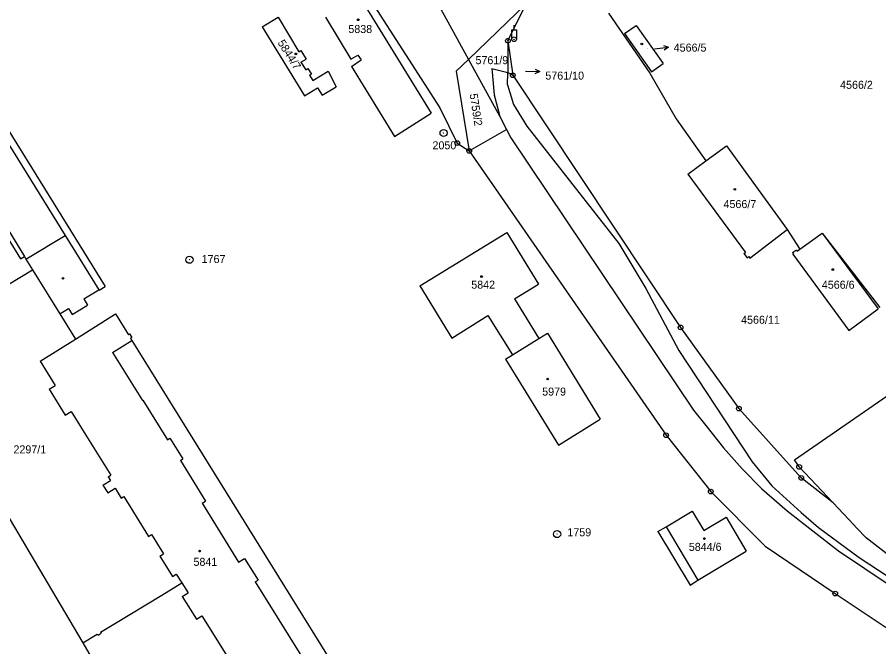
# Model space of a CAD drawing. Extents: x -735092 to -733385, y -1122435 to -1118992.
# Drawn here: x -734684.8 to -734501.9, y -1119739.8 to -1119606.1 of the extents above; entities that cross this region are included whole.
import ezdxf

# ---------------------------------------------------------------- set-up
doc = ezdxf.new("R2010")
doc.units = 0
for name, color, linetype in [('Vrstva 1', 7, 'Continuous'), ('Vrstva 16', 7, 'Continuous'), ('Vrstva 17', 7, 'Continuous'), ('Vrstva 18', 7, 'Continuous'), ('Vrstva 19', 7, 'Continuous'), ('Vrstva 25', 7, 'Continuous'), ('Vrstva 4', 7, 'Continuous')]:
    doc.layers.add(name, color=color, linetype=linetype)

msp = doc.modelspace()

# ---------------------------------------------------------------- linework, layer by layer
at = {"layer": 'Vrstva 1'}
for points in [[(-734660.68, -1119523.3), (-734595.14, -1119625.34)], [(-734623.05, -1119583.97), (-734596.92, -1119626.44)], [(-734594.97, -1119604.22), (-734589.04, -1119615.1)], [(-734589.04, -1119615.1), (-734576.81, -1119603.24)], [(-734580.65, -1119611.1), (-734576.81, -1119603.24)], [(-734632.81, -1119608.14), (-734629.42, -1119606.11)], [(-734629.42, -1119606.11), (-734625.03, -1119613.42)], [(-734619.38, -1119606.09), (-734613.98, -1119615)], [(-734559.31, -1119605.21), (-734550.5, -1119617.96)], [(-734632.81, -1119608.14), (-734623.86, -1119622.77)], [(-734555.91, -1119609.56), (-734553.46, -1119607.83)], [(-734553.46, -1119607.83), (-734547.72, -1119615.95)], [(-734699.69, -1119609.22), (-734666.16, -1119663.28)], [(-734555.91, -1119609.56), (-734550.15, -1119617.72)], [(-734580.65, -1119611.1), (-734580.64, -1119617.85)], [(-734580.65, -1119611.1), (-734579.63, -1119618.42)], [(-734711.44, -1119613.13), (-734684.16, -1119657.42)], [(-734625.03, -1119613.42), (-734624.59, -1119613.16)], [(-734624.59, -1119613.16), (-734623.51, -1119614.98)], [(-734624.59, -1119615.66), (-734623.51, -1119614.98)], [(-734624.59, -1119615.66), (-734623.53, -1119617.29)], [(-734613.98, -1119615), (-734612.53, -1119614.15)], [(-734613.85, -1119616.54), (-734611.81, -1119615.17)], [(-734612.53, -1119614.15), (-734611.81, -1119615.17)], [(-734591.62, -1119617.58), (-734589.04, -1119615.1)], [(-734589.04, -1119615.1), (-734582.37, -1119627.21)], [(-734623.53, -1119617.29), (-734623.12, -1119617.02)], [(-734623.12, -1119617.02), (-734622.38, -1119618.17)], [(-734622.1, -1119619.51), (-734618.81, -1119617.53)], [(-734618.81, -1119617.53), (-734617.09, -1119620.85)], [(-734613.85, -1119616.54), (-734604.74, -1119631.41)], [(-734591.62, -1119617.58), (-734588.87, -1119634.49)], [(-734584.05, -1119617.02), (-734580.64, -1119617.85)], [(-734584.05, -1119617.02), (-734583.56, -1119622.59)], [(-734550.15, -1119617.72), (-734547.72, -1119615.95)], [(-734622.79, -1119618.44), (-734622.38, -1119618.17)], [(-734622.79, -1119618.44), (-734622.1, -1119619.51)], [(-734580.73, -1119620.47), (-734580.64, -1119617.85)], [(-734580.64, -1119617.85), (-734579.63, -1119618.42)], [(-734579.63, -1119618.42), (-734544, -1119671.99)], [(-734550.5, -1119617.96), (-734544.96, -1119627.7)], [(-734623.86, -1119622.77), (-734621.05, -1119621.12)], [(-734621.05, -1119621.12), (-734620.07, -1119622.68)], [(-734620.07, -1119622.68), (-734617.09, -1119620.85)], [(-734580.73, -1119620.47), (-734579.45, -1119624.63)], [(-734583.56, -1119622.59), (-734582.37, -1119627.21)], [(-734579.45, -1119624.63), (-734576.65, -1119629.22)], [(-734604.74, -1119631.41), (-734596.92, -1119626.44)], [(-734595.14, -1119625.34), (-734591.41, -1119632.82)], [(-734582.37, -1119627.21), (-734580.99, -1119629.91)], [(-734544.96, -1119627.7), (-734538.6, -1119636.58)], [(-734588.87, -1119634.49), (-734580.99, -1119629.91)], [(-734580.99, -1119629.91), (-734580.07, -1119631.7)], [(-734576.65, -1119629.22), (-734557.14, -1119654.13)], [(-734580.07, -1119631.7), (-734541.26, -1119689.56)], [(-734591.41, -1119632.82), (-734588.87, -1119634.49)], [(-734538.6, -1119636.58), (-734534.28, -1119633.4)], [(-734534.28, -1119633.4), (-734521.37, -1119651.2)], [(-734588.87, -1119634.49), (-734547.06, -1119694.89)], [(-734542.45, -1119639.41), (-734538.6, -1119636.58)], [(-734542.45, -1119639.41), (-734530.2, -1119656.04)], [(-734599.37, -1119663.15), (-734580.88, -1119651.83)], [(-734580.88, -1119651.83), (-734574.17, -1119662.79)], [(-734529.31, -1119657.25), (-734521.37, -1119651.2)], [(-734521.37, -1119651.2), (-734518.67, -1119655.36)], [(-734518.67, -1119655.36), (-734513.92, -1119651.95)], [(-734513.92, -1119651.95), (-734501.72, -1119667.72)], [(-734513.92, -1119651.95), (-734502.02, -1119668.05)], [(-734557.14, -1119654.13), (-734551.34, -1119663.7)], [(-734530.57, -1119656.31), (-734530.2, -1119656.04)], [(-734520.23, -1119656.09), (-734519.39, -1119655.49)], [(-734520.23, -1119656.09), (-734520.05, -1119656.35)], [(-734519.39, -1119655.49), (-734519.21, -1119655.75)], [(-734519.21, -1119655.75), (-734518.67, -1119655.36)], [(-734684.16, -1119657.42), (-734683.3, -1119656.89)], [(-734683.3, -1119656.89), (-734682.97, -1119657.5)], [(-734682.97, -1119657.5), (-734681.57, -1119659.76)], [(-734530.57, -1119656.31), (-734529.89, -1119657.22)], [(-734529.89, -1119657.22), (-734529.53, -1119656.95)], [(-734529.53, -1119656.95), (-734529.31, -1119657.25)], [(-734520.17, -1119656.44), (-734520.05, -1119656.35)], [(-734520.17, -1119656.44), (-734508.25, -1119672.65)], [(-734703.19, -1119672.77), (-734681.57, -1119659.76)], [(-734681.57, -1119659.76), (-734675.78, -1119669.11)], [(-734667.46, -1119664.09), (-734666.16, -1119663.28)], [(-734599.37, -1119663.15), (-734592.56, -1119674.23)], [(-734579.25, -1119665.91), (-734574.17, -1119662.79)], [(-734670.72, -1119665.94), (-734667.53, -1119663.98)], [(-734667.53, -1119663.98), (-734667.46, -1119664.09)], [(-734551.34, -1119663.7), (-734544.35, -1119676.91)], [(-734670.72, -1119665.94), (-734669.92, -1119667.24)], [(-734579.25, -1119665.91), (-734574.1, -1119674.32)], [(-734675.78, -1119669.11), (-734673.93, -1119667.96)], [(-734673.93, -1119667.96), (-734673.15, -1119669.22)], [(-734673.15, -1119669.22), (-734669.92, -1119667.24)], [(-734508.25, -1119672.65), (-734502.02, -1119668.05)], [(-734675.78, -1119669.11), (-734672.47, -1119674.44)], [(-734672.47, -1119674.44), (-734663.95, -1119669.12)], [(-734663.95, -1119669.12), (-734661.23, -1119673.52)], [(-734592.56, -1119674.23), (-734584.89, -1119669.48)], [(-734584.89, -1119669.48), (-734579.71, -1119677.82)], [(-734544, -1119671.99), (-734531.62, -1119689.2)], [(-734661.23, -1119673.52), (-734661, -1119673.37)], [(-734661, -1119673.37), (-734660.53, -1119674.14)], [(-734660.76, -1119674.28), (-734660.53, -1119674.14)], [(-734660.76, -1119674.28), (-734660.48, -1119674.74)], [(-734579.71, -1119677.82), (-734574.1, -1119674.32)], [(-734574.1, -1119674.32), (-734572.26, -1119673.2)], [(-734572.26, -1119673.2), (-734561.06, -1119691.49)], [(-734679.99, -1119679.14), (-734672.47, -1119674.44)], [(-734660.48, -1119674.74), (-734611.9, -1119753.15)], [(-734581.14, -1119678.71), (-734579.71, -1119677.82)], [(-734544.35, -1119676.91), (-734528.81, -1119700.51)], [(-734706.85, -1119678.19), (-734670.91, -1119738.99)], [(-734679.99, -1119679.14), (-734676.78, -1119684.32)], [(-734581.14, -1119678.71), (-734569.89, -1119697)], [(-734519.81, -1119700.1), (-734492.14, -1119681)], [(-734678.04, -1119685.12), (-734676.78, -1119684.32)], [(-734678.04, -1119685.12), (-734674.65, -1119690.62)], [(-734674.65, -1119690.62), (-734673.38, -1119689.84)], [(-734673.38, -1119689.84), (-734670.25, -1119694.89)], [(-734541.26, -1119689.56), (-734538.64, -1119692.79)], [(-734531.62, -1119689.2), (-734518.37, -1119703.93)], [(-734569.89, -1119697), (-734561.06, -1119691.49)], [(-734538.64, -1119692.79), (-734534.86, -1119697.53)], [(-734670.25, -1119694.89), (-734664.97, -1119703.34)], [(-734547.06, -1119694.89), (-734537.59, -1119706.84)], [(-734534.86, -1119697.53), (-734530.92, -1119701.99)], [(-734528.81, -1119700.51), (-734524.6, -1119705.59)], [(-734518.82, -1119701.59), (-734519.81, -1119700.1)], [(-734518.82, -1119701.59), (-734511.58, -1119709.24)], [(-734665.53, -1119703.69), (-734664.97, -1119703.34)], [(-734530.92, -1119701.99), (-734526.75, -1119706.28)], [(-734666.63, -1119705.48), (-734665.04, -1119704.48)], [(-734666.63, -1119705.48), (-734665.59, -1119707.1)], [(-734665.53, -1119703.69), (-734665.04, -1119704.48)], [(-734511.58, -1119709.24), (-734518.37, -1119703.93)], [(-734665.59, -1119707.1), (-734664.02, -1119706.13)], [(-734664.02, -1119706.13), (-734662.73, -1119708.21)], [(-734537.59, -1119706.84), (-734526.03, -1119718.42)], [(-734526.75, -1119706.28), (-734521.36, -1119710.95)], [(-734524.6, -1119705.59), (-734518.4, -1119711.28)], [(-734662.73, -1119708.21), (-734662.17, -1119707.87)], [(-734662.17, -1119707.87), (-734656.97, -1119716.37)], [(-734521.36, -1119710.95), (-734510.5, -1119719.43)], [(-734507.2, -1119713.87), (-734511.58, -1119709.24)], [(-734547.07, -1119714.35), (-734541.56, -1119711.01)], [(-734541.56, -1119711.01), (-734539.06, -1119715.14)], [(-734539.06, -1119715.14), (-734534.34, -1119712.29)], [(-734534.34, -1119712.29), (-734530.04, -1119719.49)], [(-734518.4, -1119711.28), (-734514.73, -1119714.46)], [(-734548.8, -1119715.32), (-734547.07, -1119714.35)], [(-734514.73, -1119714.46), (-734506.11, -1119720.81)], [(-734506.62, -1119714.52), (-734507.2, -1119713.87)], [(-734504.62, -1119716.69), (-734506.62, -1119714.52)], [(-734656.97, -1119716.37), (-734656.32, -1119715.96)], [(-734656.32, -1119715.96), (-734653.76, -1119720.06)], [(-734548.8, -1119715.32), (-734541.97, -1119726.69)], [(-734498.58, -1119721.37), (-734504.62, -1119716.69)], [(-734654.57, -1119720.56), (-734653.76, -1119720.06)], [(-734540.3, -1119725.63), (-734530.04, -1119719.49)], [(-734526.03, -1119718.42), (-734511.16, -1119728.49)], [(-734510.5, -1119719.43), (-734487.9, -1119734.54)], [(-734654.57, -1119720.56), (-734651.9, -1119724.88)], [(-734506.11, -1119720.81), (-734481.7, -1119736.85)], [(-734651.9, -1119724.88), (-734651.08, -1119724.37)], [(-734651.08, -1119724.37), (-734649.89, -1119726.25)], [(-734541.97, -1119726.69), (-734540.3, -1119725.63)], [(-734654.16, -1119728.85), (-734649.89, -1119726.25)], [(-734649.89, -1119726.25), (-734648.56, -1119728.37)], [(-734664.34, -1119735.01), (-734654.16, -1119728.85)], [(-734649.78, -1119729.13), (-734648.56, -1119728.37)], [(-734649.78, -1119729.13), (-734646.79, -1119733.94)], [(-734511.16, -1119728.49), (-734483.78, -1119746.72)], [(-734646.79, -1119733.94), (-734645.65, -1119733.23)], [(-734645.65, -1119733.23), (-734634.05, -1119751.76)], [(-734667.12, -1119736.7), (-734664.34, -1119735.01)], [(-734670.91, -1119738.99), (-734667.84, -1119737.13)], [(-734667.84, -1119737.13), (-734667.62, -1119737.3)], [(-734667.62, -1119737.3), (-734666.99, -1119736.91)], [(-734667.12, -1119736.7), (-734666.99, -1119736.91)], [(-734670.91, -1119738.99), (-734661.3, -1119755.55)]]:
    msp.add_lwpolyline(points, dxfattribs=at)
at = {"layer": 'Vrstva 25'}
for points in [[(-734579.35, -1119608.79), (-734579.35, -1119607.79)], [(-734579.85, -1119610.79), (-734579.85, -1119608.79), (-734578.85, -1119608.79), (-734578.85, -1119610.79)], [(-734547.638, -1119612.087), (-734546.584, -1119612.46), (-734547.514, -1119613.078)], [(-734549.56, -1119612.83), (-734546.584, -1119612.46)], [(-734576.91, -1119617.54), (-734573.912, -1119617.644)], [(-734574.894, -1119617.111), (-734573.912, -1119617.644), (-734574.929, -1119618.109)]]:
    msp.add_lwpolyline(points, dxfattribs=at)
for centre, radius in [((-734612.43, -1119606.65), 0.175), ((-734579.35, -1119610.79), 0.5), ((-734580.65, -1119611.1), 0.5), ((-734580.65, -1119611.1), 0.032), ((-734579.35, -1119610.79), 0.05), ((-734552.24, -1119611.78), 0.175), ((-734625.67, -1119613.89), 0.174), ((-734579.63, -1119618.42), 0.5), ((-734579.63, -1119618.42), 0.032), ((-734594.32, -1119630.68), 0.75), ((-734594.32, -1119630.68), 0.032), ((-734591.41, -1119632.82), 0.5), ((-734591.41, -1119632.82), 0.032), ((-734588.87, -1119634.49), 0.5), ((-734588.87, -1119634.49), 0.032), ((-734532.48, -1119642.64), 0.175), ((-734648.26, -1119657.61), 0.75), ((-734648.26, -1119657.61), 0.032), ((-734511.69, -1119659.68), 0.175), ((-734675.13, -1119661.56), 0.175), ((-734586.26, -1119661.18), 0.175), ((-734544, -1119671.99), 0.5), ((-734544, -1119671.99), 0.032), ((-734572.21, -1119682.94), 0.175), ((-734531.62, -1119689.2), 0.5), ((-734531.62, -1119689.2), 0.032), ((-734547.06, -1119694.89), 0.5), ((-734547.06, -1119694.89), 0.032), ((-734518.82, -1119701.59), 0.5), ((-734518.82, -1119701.59), 0.032), ((-734518.37, -1119703.93), 0.5), ((-734518.37, -1119703.93), 0.032), ((-734537.59, -1119706.84), 0.5), ((-734537.59, -1119706.84), 0.032), ((-734570.2, -1119715.87), 0.75), ((-734570.2, -1119715.87), 0.032), ((-734538.95, -1119716.82), 0.175), ((-734646.11, -1119719.48), 0.175), ((-734511.16, -1119728.49), 0.5), ((-734511.16, -1119728.49), 0.032)]:
    msp.add_circle(centre, radius, dxfattribs=at)
at = {"layer": 'Vrstva 4'}
for points in [[(-734701.04, -1119609.9), (-734674.67, -1119652.46)], [(-734708.92, -1119615.03), (-734683.3, -1119656.89)], [(-734682.97, -1119657.5), (-734674.67, -1119652.46)], [(-734674.67, -1119652.46), (-734667.53, -1119663.98)], [(-734664.59, -1119677.28), (-734660.48, -1119674.74)], [(-734664.59, -1119677.28), (-734658.24, -1119687.52)], [(-734658.24, -1119687.52), (-734658.15, -1119687.46)], [(-734658.15, -1119687.46), (-734652.96, -1119695.84)], [(-734652.96, -1119695.84), (-734652.4, -1119695.5)], [(-734652.4, -1119695.5), (-734649.66, -1119699.92)], [(-734650.2, -1119700.25), (-734649.66, -1119699.92)], [(-734650.2, -1119700.25), (-734647.93, -1119703.9)], [(-734647.93, -1119703.9), (-734644.86, -1119708.86)], [(-734645.59, -1119709.31), (-734644.86, -1119708.86)], [(-734645.59, -1119709.31), (-734637.83, -1119721.81)], [(-734547.07, -1119714.35), (-734540.3, -1119725.63)], [(-734637.83, -1119721.81), (-734636.58, -1119721.03)], [(-734636.58, -1119721.03), (-734633.69, -1119725.66)], [(-734634.29, -1119726.03), (-734633.69, -1119725.66)], [(-734634.29, -1119726.03), (-734622.62, -1119744.76)]]:
    msp.add_lwpolyline(points, dxfattribs=at)

# ---------------------------------------------------------------- texts
at = {"layer": 'Vrstva 16'}
for s, p in [('4566/5', (-734545.46, -1119613.4)), ('5761/10', (-734572.71, -1119619.35))]:
    msp.add_text(s, height=1.7, dxfattribs=at).set_placement(p)
at = {"layer": 'Vrstva 17'}
for s, p in [('2050', (-734596.67, -1119634.15)), ('1767', (-734645.68, -1119658.3)), ('1759', (-734568.03, -1119716.33))]:
    msp.add_text(s, height=1.7, dxfattribs=at).set_placement(p)
at = {"layer": 'Vrstva 18'}
for s, p in [('5761/9', (-734587.54, -1119616.07)), ('4566/2', (-734510.13, -1119621.3)), ('4566/11', (-734531.148, -1119671.2)), ('2297/1', (-734685.63, -1119698.73))]:
    msp.add_text(s, height=1.7, dxfattribs=at).set_placement(p)
for s, height, rotation, p in [('5761/10', 0.1, 54.70044, (-734580.417, -1119617.142)), ('5759/2', 1.7, 278.80222, (-734588.792, -1119622.427))]:
    msp.add_text(s, height=height, rotation=rotation, dxfattribs=at).set_placement(p)
at = {"layer": 'Vrstva 19'}
for s, height, p in [('5838', 1.7, (-734614.53, -1119609.45)), ('4566/5', 0.1, (-734551.23, -1119612.86)), ('4566/7', 1.7, (-734534.88, -1119646.63)), ('5842', 1.7, (-734588.44, -1119663.75)), ('4566/6', 1.7, (-734514.01, -1119663.76)), ('5979', 1.7, (-734573.38, -1119686.46)), ('5844/6', 1.7, (-734542.25, -1119719.43)), ('5841', 1.7, (-734647.41, -1119722.61))]:
    msp.add_text(s, height=height, dxfattribs=at).set_placement(p)
msp.add_text('5844/7', height=1.7, rotation=302.2024, dxfattribs=at).set_placement((-734629.625, -1119611.532))

doc.saveas('drawing.dxf')
